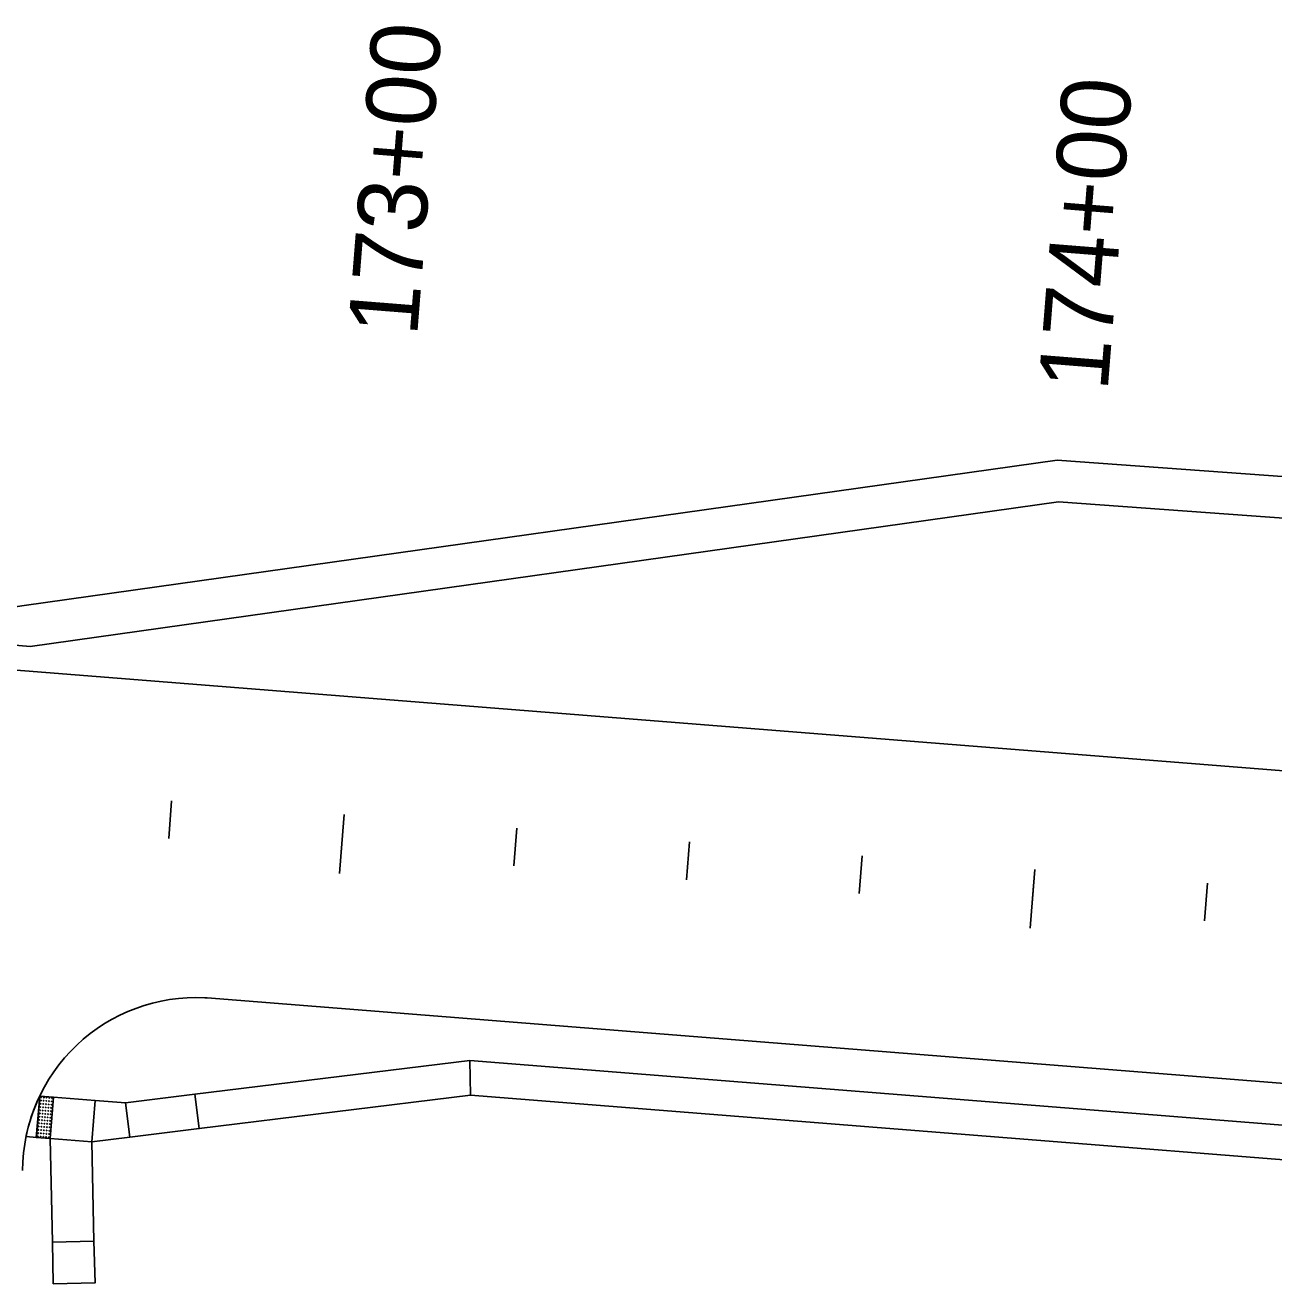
# Model space of a CAD drawing. Extents: x 20499216 to 20505321, y 7953487 to 7960535.
# Drawn here: x 20500965.4 to 20501145.7, y 7953893.9 to 7954075.5 of the extents above; entities that cross this region are included whole.
import ezdxf

# ---------------------------------------------------------------- set-up
doc = ezdxf.new("R2010")
doc.units = 0
for name, color, linetype in [('Drainage', 7, 'Continuous'), ('EXT_CU', 7, 'Continuous'), ('EXT_RR', 7, 'Continuous'), ('NamedBoundary', 7, 'Continuous'), ('Roadways', 7, 'Continuous'), ('Safety', 7, 'Continuous')]:
    doc.layers.add(name, color=color, linetype=linetype)

msp = doc.modelspace()

# ---------------------------------------------------------------- linework, layer by layer
at = {"layer": 'Drainage'}
for points in [[(20500979.93, 7953919.99), (20500980.54, 7953915.03), (20500975.06, 7953914.36), (20500975.53, 7953920.34)], [(20500980.52, 7953915.03), (20500979.91, 7953919.99), (20500989.95, 7953921.22), (20500990.56, 7953916.26)]]:
    msp.add_lwpolyline(points, close=True, dxfattribs=at)
at = {"layer": 'EXT_CU'}
for p, q in [((20500967.04, 7953914.99), (20500967.53, 7953920.97)), ((20500967.53, 7953920.97), (20500969.52, 7953920.82)), ((20500969.52, 7953920.82), (20500969.04, 7953914.84)), ((20500969.04, 7953914.84), (20500967.04, 7953914.99))]:
    msp.add_line(p, q, dxfattribs=at)
for points in [[(20500965.3, 7953991.78), (20501114.4, 7954012.75), (20501316.65, 7953998.09), (20501476.2, 7953950.79), (20501496.14, 7953949.21), (20501511.25, 7953950.02), (20501604.78, 7953942.58), (20501718.78, 7953932.38), (20501718.33, 7953927.4), (20501604.36, 7953937.6), (20501511.18, 7953945), (20501496.07, 7953944.2), (20501475.28, 7953945.85), (20501320.22, 7953991.82), (20501114.61, 7954006.72), (20500966.14, 7953985.84), (20500961.2, 7953986.29), (20500961.66, 7953991.27)], [(20501029.61, 7953926.09), (20501029.72, 7953921.07), (20500990.56, 7953916.26), (20500989.95, 7953921.22)], [(20501029.61, 7953926.09), (20501232.28, 7953909.99), (20501231.88, 7953905), (20501029.72, 7953921.07)], [(20500975.06, 7953914.36), (20500975.36, 7953900.02), (20500969.36, 7953899.86), (20500969.05, 7953914.83)], [(20500969.36, 7953899.86), (20500975.36, 7953900.02), (20500975.54, 7953894.02), (20500969.49, 7953893.86)]]:
    msp.add_lwpolyline(points, close=True, dxfattribs=at)
for centre, major_axis in [((20500967.7, 7953920.32), (-0.0038, -0.0448)), ((20500967.7, 7953920.32), (-0.0019, -0.0224)), ((20500967.74, 7953920.79), (-0.0038, -0.0448)), ((20500967.74, 7953920.79), (-0.0019, -0.0224)), ((20500968.09, 7953920.29), (-0.0038, -0.0448)), ((20500968.09, 7953920.29), (-0.0019, -0.0224)), ((20500968.13, 7953920.76), (-0.0038, -0.0448)), ((20500968.13, 7953920.76), (-0.0019, -0.0224)), ((20500968.48, 7953920.26), (-0.0038, -0.0448)), ((20500968.48, 7953920.26), (-0.0019, -0.0224)), ((20500968.52, 7953920.73), (-0.0038, -0.0448)), ((20500968.52, 7953920.73), (-0.0019, -0.0224)), ((20500968.87, 7953920.23), (-0.0038, -0.0448)), ((20500968.87, 7953920.23), (-0.0019, -0.0224)), ((20500968.91, 7953920.69), (-0.0038, -0.0448)), ((20500968.91, 7953920.69), (-0.0019, -0.0224)), ((20500969.26, 7953920.19), (-0.0038, -0.0448)), ((20500969.26, 7953920.19), (-0.0019, -0.0224)), ((20500969.3, 7953920.66), (-0.0038, -0.0448)), ((20500969.3, 7953920.66), (-0.0019, -0.0224)), ((20500967.55, 7953918.45), (-0.0038, -0.0448)), ((20500967.55, 7953918.45), (-0.0019, -0.0224)), ((20500967.58, 7953918.91), (-0.0038, -0.0448)), ((20500967.58, 7953918.91), (-0.0019, -0.0224)), ((20500967.62, 7953919.38), (-0.0038, -0.0448)), ((20500967.62, 7953919.38), (-0.0019, -0.0224)), ((20500967.66, 7953919.85), (-0.0038, -0.0448)), ((20500967.66, 7953919.85), (-0.0019, -0.0224)), ((20500967.94, 7953918.41), (-0.0038, -0.0448)), ((20500967.94, 7953918.41), (-0.0019, -0.0224)), ((20500967.97, 7953918.88), (-0.0038, -0.0448)), ((20500967.97, 7953918.88), (-0.0019, -0.0224)), ((20500968.01, 7953919.35), (-0.0038, -0.0448)), ((20500968.01, 7953919.35), (-0.0019, -0.0224)), ((20500968.05, 7953919.82), (-0.0038, -0.0448)), ((20500968.05, 7953919.82), (-0.0019, -0.0224)), ((20500968.33, 7953918.38), (-0.0038, -0.0448)), ((20500968.33, 7953918.38), (-0.0019, -0.0224)), ((20500968.36, 7953918.85), (-0.0038, -0.0448)), ((20500968.36, 7953918.85), (-0.0019, -0.0224)), ((20500968.4, 7953919.32), (-0.0038, -0.0448)), ((20500968.4, 7953919.32), (-0.0019, -0.0224)), ((20500968.44, 7953919.79), (-0.0038, -0.0448)), ((20500968.44, 7953919.79), (-0.0019, -0.0224)), ((20500968.76, 7953918.82), (-0.0038, -0.0448)), ((20500968.76, 7953918.82), (-0.0019, -0.0224)), ((20500968.79, 7953919.29), (-0.0038, -0.0448)), ((20500968.79, 7953919.29), (-0.0019, -0.0224)), ((20500968.83, 7953919.76), (-0.0038, -0.0448)), ((20500968.83, 7953919.76), (-0.0019, -0.0224)), ((20500969.15, 7953918.79), (-0.0038, -0.0448)), ((20500969.15, 7953918.79), (-0.0019, -0.0224)), ((20500969.18, 7953919.26), (-0.0038, -0.0448)), ((20500969.18, 7953919.26), (-0.0019, -0.0224)), ((20500969.22, 7953919.73), (-0.0038, -0.0448)), ((20500969.22, 7953919.73), (-0.0019, -0.0224)), ((20500967.39, 7953916.57), (-0.0038, -0.0448)), ((20500967.39, 7953916.57), (-0.0019, -0.0224)), ((20500967.43, 7953917.04), (-0.0038, -0.0448)), ((20500967.43, 7953917.04), (-0.0019, -0.0224)), ((20500967.47, 7953917.51), (-0.0038, -0.0448)), ((20500967.47, 7953917.51), (-0.0019, -0.0224)), ((20500967.51, 7953917.98), (-0.0038, -0.0448)), ((20500967.51, 7953917.98), (-0.0019, -0.0224)), ((20500967.78, 7953916.54), (-0.0038, -0.0448)), ((20500967.82, 7953917.01), (-0.0038, -0.0448)), ((20500967.82, 7953917.01), (-0.0019, -0.0224)), ((20500967.86, 7953917.48), (-0.0038, -0.0448)), ((20500967.86, 7953917.48), (-0.0019, -0.0224)), ((20500967.9, 7953917.95), (-0.0038, -0.0448)), ((20500967.9, 7953917.95), (-0.0019, -0.0224)), ((20500968.21, 7953916.98), (-0.0038, -0.0448)), ((20500968.21, 7953916.98), (-0.0019, -0.0224)), ((20500968.25, 7953917.45), (-0.0038, -0.0448)), ((20500968.25, 7953917.45), (-0.0019, -0.0224)), ((20500968.29, 7953917.92), (-0.0038, -0.0448)), ((20500968.29, 7953917.92), (-0.0019, -0.0224)), ((20500968.6, 7953916.95), (-0.0038, -0.0448)), ((20500968.6, 7953916.95), (-0.0019, -0.0224)), ((20500968.64, 7953917.42), (-0.0038, -0.0448)), ((20500968.64, 7953917.42), (-0.0019, -0.0224)), ((20500968.68, 7953917.88), (-0.0038, -0.0448)), ((20500968.68, 7953917.88), (-0.0019, -0.0224)), ((20500968.72, 7953918.35), (-0.0038, -0.0448)), ((20500968.72, 7953918.35), (-0.0019, -0.0224)), ((20500968.99, 7953916.92), (-0.0038, -0.0448)), ((20500968.99, 7953916.92), (-0.0019, -0.0224)), ((20500969.03, 7953917.38), (-0.0038, -0.0448)), ((20500969.03, 7953917.38), (-0.0019, -0.0224)), ((20500969.07, 7953917.85), (-0.0038, -0.0448)), ((20500969.07, 7953917.85), (-0.0019, -0.0224)), ((20500969.11, 7953918.32), (-0.0038, -0.0448)), ((20500969.11, 7953918.32), (-0.0019, -0.0224)), ((20500967.28, 7953915.14), (-0.0038, -0.0448)), ((20500967.28, 7953915.14), (-0.0019, -0.0224)), ((20500967.32, 7953915.61), (-0.0038, -0.0448)), ((20500967.32, 7953915.61), (-0.0019, -0.0224)), ((20500967.35, 7953916.08), (-0.0038, -0.0448)), ((20500967.35, 7953916.08), (-0.0019, -0.0224)), ((20500967.67, 7953915.11), (-0.0038, -0.0448)), ((20500967.67, 7953915.11), (-0.0019, -0.0224)), ((20500967.71, 7953915.58), (-0.0038, -0.0448)), ((20500967.71, 7953915.58), (-0.0019, -0.0224)), ((20500967.74, 7953916.05), (-0.0038, -0.0448)), ((20500967.74, 7953916.05), (-0.0019, -0.0224)), ((20500967.78, 7953916.54), (-0.0019, -0.0224)), ((20500968.06, 7953915.08), (-0.0038, -0.0448)), ((20500968.06, 7953915.08), (-0.0019, -0.0224)), ((20500968.1, 7953915.55), (-0.0038, -0.0448)), ((20500968.1, 7953915.55), (-0.0019, -0.0224)), ((20500968.14, 7953916.02), (-0.0038, -0.0448)), ((20500968.14, 7953916.02), (-0.0019, -0.0224)), ((20500968.18, 7953916.51), (-0.0038, -0.0448)), ((20500968.18, 7953916.51), (-0.0019, -0.0224)), ((20500968.45, 7953915.05), (-0.0038, -0.0448)), ((20500968.45, 7953915.05), (-0.0019, -0.0224)), ((20500968.49, 7953915.52), (-0.0038, -0.0448)), ((20500968.49, 7953915.52), (-0.0019, -0.0224)), ((20500968.53, 7953915.99), (-0.0038, -0.0448)), ((20500968.53, 7953915.99), (-0.0019, -0.0224)), ((20500968.57, 7953916.48), (-0.0038, -0.0448)), ((20500968.57, 7953916.48), (-0.0019, -0.0224)), ((20500968.84, 7953915.02), (-0.0038, -0.0448)), ((20500968.84, 7953915.02), (-0.0019, -0.0224)), ((20500968.88, 7953915.49), (-0.0038, -0.0448)), ((20500968.88, 7953915.49), (-0.0019, -0.0224)), ((20500968.92, 7953915.95), (-0.0038, -0.0448)), ((20500968.92, 7953915.95), (-0.0019, -0.0224)), ((20500968.96, 7953916.45), (-0.0038, -0.0448)), ((20500968.96, 7953916.45), (-0.0019, -0.0224))]:
    msp.add_ellipse(centre, major_axis=major_axis, ratio=0.833333, dxfattribs=at)
at = {"layer": 'EXT_RR'}
for p, q in [((20500986.15, 7953958.14), (20500986.58, 7953963.58)), ((20501011.31, 7953959.21), (20501010.83, 7953953.11)), ((20501035.99, 7953954.18), (20501036.43, 7953959.62)), ((20501060.91, 7953952.2), (20501061.35, 7953957.64)), ((20501085.84, 7953950.22), (20501086.27, 7953955.66)), ((20501111, 7953951.29), (20501110.51, 7953945.19)), ((20501135.68, 7953946.26), (20501136.11, 7953951.7))]:
    msp.add_line(p, q, dxfattribs=at)
at = {"layer": 'NamedBoundary'}
for points in [[(20500911.34, 7953941.51), (20500848.24, 7953946.53), (20500808.56, 7953950.16), (20500808.63, 7953950.91), (20500808.63, 7953950.91), (20500809.17, 7953955.67), (20500809.06, 7953955.68), (20500812.15, 7953989.44), (20500804.8, 7953990.07), (20500805.25, 7953995.63), (20500812.66, 7953994.97), (20500852.08, 7953991.36), (20501603.86, 7953931.62), (20501734.26, 7953919.95)], [(20501247.7, 7953914.78), (20501247.15, 7953914.83), (20501247.15, 7953914.83), (20500991.71, 7953935.12), (20500991.36, 7953935.15)]]:
    msp.add_lwpolyline(points, dxfattribs=at)
msp.add_arc((20500990.1, 7953910.15), 25.03, 87.0999, 179.8665, dxfattribs=at)
at = {"layer": 'Roadways'}
msp.add_lwpolyline([(20500967.53, 7953920.97), (20500967.05, 7953914.99), (20500965.57, 7953915.11)], dxfattribs=at)
for points in [[(20500967.05, 7953914.99), (20500967.53, 7953920.97), (20500969.52, 7953920.82), (20500969.05, 7953914.83), (20500969.05, 7953914.83)], [(20500975.53, 7953920.34), (20500975.06, 7953914.36), (20500969.05, 7953914.83), (20500969.52, 7953920.82)]]:
    msp.add_lwpolyline(points, close=True, dxfattribs=at)
msp.add_arc((20500990.08, 7953910.18), 25, 154.4103, 168.6151, dxfattribs=at)
at = {"layer": 'Safety'}
for p, q in [((20501011.07, 7953956.16), (20501011.5, 7953961.6)), ((20501110.76, 7953948.24), (20501111.19, 7953953.68))]:
    msp.add_line(p, q, dxfattribs=at)

# ---------------------------------------------------------------- texts
at = {"layer": 'EXT_RR'}
for s, p in [('173+00', (20501022.01, 7954030.52)), ('174+00', (20501121.69, 7954022.6))]:
    msp.add_text(s, height=10.02, rotation=85.4564, dxfattribs=at).set_placement(p)

doc.saveas('drawing.dxf')
